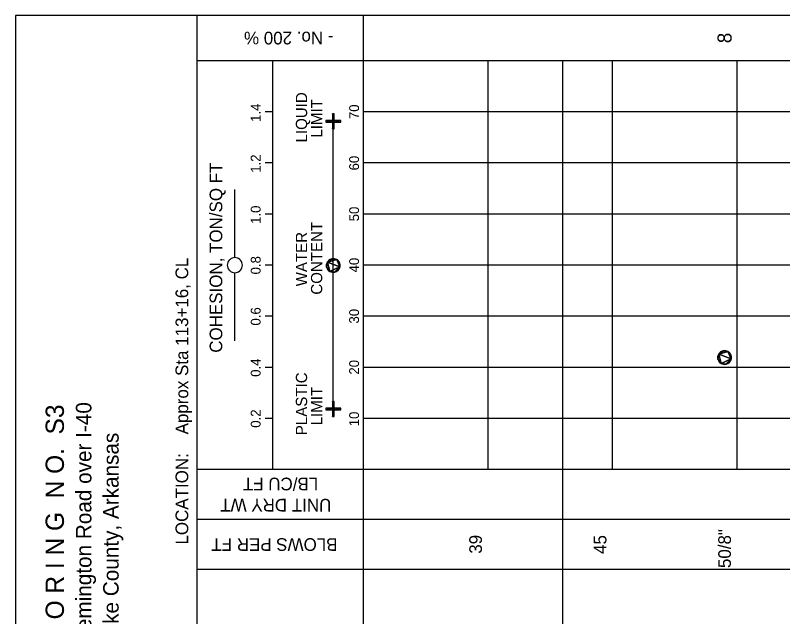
# Model space of a CAD drawing. Extents: x 1313964 to 1316843, y 2087046 to 2096619.
# Drawn here: x 1314173.48 to 1314204.3, y 2089946.89 to 2089971.04 of the extents above; entities that cross this region are included whole.
import ezdxf

# ---------------------------------------------------------------- set-up
doc = ezdxf.new("R2010")
doc.units = 0
doc.layers.add('B-Sub-Contour', color=7, linetype='Continuous')
doc.layers.add('Default', color=7, linetype='Continuous')

# ---------------------------------------------------------------- blocks, each defined once
blk = doc.blocks.new('POINT_DISPLAY')
at = {"layer": 'Default'}
blk.add_line((0, 0), (0, 0), dxfattribs=at)
blk = doc.blocks.new('DMK_101')
at = {"layer": 'Default'}
for points in [[(-14269.212, 2386.584), (-14476.476, 0), (-14269.212, -2386.584), (-14269.212, 2386.584)], [(-12638.532, 6858), (-13653.516, 4690.872), (-14269.212, 2386.584), (-12638.532, 6858)], [(-12638.532, 6858), (-14269.212, 2386.584), (-14269.212, -2386.584), (-12638.532, 6858)], [(-12638.532, 6858), (-14269.212, -2386.584), (-3147.06, -13508.736), (-12638.532, 6858)], [(-3147.06, 13511.784), (-7618.476, 11878.056), (-12638.532, 6858), (-3147.06, 13511.784)], [(6097.524, 11878.056), (-3147.06, 13511.784), (-12638.532, 6858), (6097.524, 11878.056)], [(-7618.476, 11878.056), (-11266.932, 8820.912), (-12638.532, 6858), (-7618.476, 11878.056)], [(-3147.06, -13508.736), (6097.524, 11878.056), (-12638.532, 6858), (-3147.06, -13508.736)], [(-7618.476, 11878.056), (-9578.34, 10506.456), (-11266.932, 8820.912), (-7618.476, 11878.056)], [(-9578.34, 10506.456), (-10456.164, 9698.736), (-11266.932, 8820.912), (-9578.34, 10506.456)], [(-3147.06, 13511.784), (-5451.348, 12893.04), (-7618.476, 11878.056), (-3147.06, 13511.784)], [(1626.108, 13511.784), (-760.476, 13712.952), (-3147.06, 13511.784), (1626.108, 13511.784)], [(6097.524, 11878.056), (1626.108, 13511.784), (-3147.06, 13511.784), (6097.524, 11878.056)], [(-3147.06, -13508.736), (11117.58, -6858), (6097.524, 11878.056), (-3147.06, -13508.736)], [(6097.524, 11878.056), (3930.396, 12893.04), (1626.108, 13511.784), (6097.524, 11878.056)], [(11117.58, 6858), (8060.436, 10506.456), (6097.524, 11878.056), (11117.58, 6858)], [(12751.308, 2386.584), (11117.58, 6858), (6097.524, 11878.056), (12751.308, 2386.584)], [(11117.58, -6858), (12751.308, 2386.584), (6097.524, 11878.056), (11117.58, -6858)], [(9745.98, 8820.912), (8938.26, 9698.736), (8060.436, 10506.456), (9745.98, 8820.912)], [(11117.58, 6858), (9745.98, 8820.912), (8060.436, 10506.456), (11117.58, 6858)], [(12751.308, 2386.584), (12132.564, 4690.872), (11117.58, 6858), (12751.308, 2386.584)], [(11117.58, -6858), (12751.308, -2386.584), (12751.308, 2386.584), (11117.58, -6858)], [(12751.308, -2386.584), (12952.476, 0), (12751.308, 2386.584), (12751.308, -2386.584)], [(-14269.212, -2386.584), (-13653.516, -4690.872), (-12638.532, -6858), (-14269.212, -2386.584)], [(-14269.212, -2386.584), (-12638.532, -6858), (-9578.34, -10506.456), (-14269.212, -2386.584)], [(-14269.212, -2386.584), (-9578.34, -10506.456), (-3147.06, -13508.736), (-14269.212, -2386.584)], [(-12638.532, -6858), (-11266.932, -8817.864), (-9578.34, -10506.456), (-12638.532, -6858)], [(-11266.932, -8817.864), (-10456.164, -9695.688), (-9578.34, -10506.456), (-11266.932, -8817.864)], [(-9578.34, -10506.456), (-7618.476, -11878.056), (-3147.06, -13508.736), (-9578.34, -10506.456)], [(-7618.476, -11878.056), (-5451.348, -12893.04), (-3147.06, -13508.736), (-7618.476, -11878.056)], [(-3147.06, -13508.736), (6097.524, -11878.056), (11117.58, -6858), (-3147.06, -13508.736)], [(-3147.06, -13508.736), (1626.108, -13508.736), (6097.524, -11878.056), (-3147.06, -13508.736)], [(-3147.06, -13508.736), (-760.476, -13716), (1626.108, -13508.736), (-3147.06, -13508.736)], [(1626.108, -13508.736), (3930.396, -12893.04), (6097.524, -11878.056), (1626.108, -13508.736)], [(6097.524, -11878.056), (8060.436, -10506.456), (11117.58, -6858), (6097.524, -11878.056)], [(8060.436, -10506.456), (9745.98, -8817.864), (11117.58, -6858), (8060.436, -10506.456)], [(8060.436, -10506.456), (8938.26, -9695.688), (9745.98, -8817.864), (8060.436, -10506.456)], [(11117.58, -6858), (12132.564, -4690.872), (12751.308, -2386.584), (11117.58, -6858)]]:
    blk.add_lwpolyline(points, close=True, dxfattribs=at)
blk.add_blockref('POINT_DISPLAY', (14479.524, 0), dxfattribs=at)
blk = doc.blocks.new('DMK_7')
at = {"layer": 'Default'}
blk.add_lwpolyline([(0, -15240), (2651.76, -15011.4), (5212.08, -14325.6), (7620, -13197.84), (9799.32, -11673.84), (10774.68, -10774.68), (11673.84, -9799.32), (13197.84, -7620), (14325.6, -5212.08), (15011.4, -2651.76), (15240, 0), (15011.4, 2651.76), (14325.6, 5212.08), (13197.84, 7620), (11673.84, 9799.32), (10774.68, 10774.68), (9799.32, 11673.84), (7620, 13197.84), (5212.08, 14325.6), (2651.76, 15011.4), (0, 15240), (-2651.76, 15011.4), (-5212.08, 14325.6), (-7620, 13197.84), (-9799.32, 11673.84), (-10774.68, 10774.68), (-11673.84, 9799.32), (-13197.84, 7620), (-14325.6, 5212.08), (-15011.4, 2651.76), (-15240, 0), (-15011.4, -2651.76), (-14325.6, -5212.08), (-13197.84, -7620), (-11673.84, -9799.32), (-10774.68, -10774.68), (-9799.32, -11673.84), (-7620, -13197.84), (-5212.08, -14325.6), (-2651.76, -15011.4), (0, -15240)], dxfattribs=at)
blk = doc.blocks.new('DMK_99')
at = {"layer": 'Default'}
for points in [[(-1524, -1524), (-1524, 1524), (-15240, 1524), (-1524, -1524)], [(-1524, -1524), (-15240, 1524), (-15240, -1524), (-1524, -1524)], [(1524, 1524), (1524, 15240), (-1524, 15240), (1524, 1524)], [(1524, 1524), (-1524, 15240), (-1524, 1524), (1524, 1524)], [(-1524, -1524), (1524, -1524), (1524, 1524), (-1524, -1524)], [(-1524, -1524), (1524, 1524), (-1524, 1524), (-1524, -1524)], [(1524, -1524), (15240, -1524), (15240, 1524), (1524, -1524)], [(1524, -1524), (15240, 1524), (1524, 1524), (1524, -1524)], [(-1524, -1524), (-1524, -15240), (1524, -15240), (-1524, -1524)], [(-1524, -1524), (1524, -15240), (1524, -1524), (-1524, -1524)]]:
    blk.add_lwpolyline(points, close=True, dxfattribs=at)

msp = doc.modelspace()

# ---------------------------------------------------------------- linework, layer by layer
at = {"layer": 'B-Sub-Contour'}
for points in [[(1314234.904, 2089928.164), (1314234.904, 2089971.035), (1314173.485, 2089971.035), (1314173.485, 2089928.164), (1314234.904, 2089928.164)], [(1314180.782, 2089928.164), (1314180.782, 2089971.035)], [(1314187.471, 2089928.164), (1314187.471, 2089971.035)], [(1314232.471, 2089969.211), (1314180.782, 2089969.211)], [(1314183.823, 2089969.211), (1314183.519, 2089969.211)], [(1314183.823, 2089952.792), (1314183.823, 2089969.211)], [(1314232.471, 2089969.211), (1314187.471, 2089969.211)], [(1314187.471, 2089952.792), (1314187.471, 2089969.211)], [(1314192.471, 2089952.792), (1314192.471, 2089969.211)], [(1314195.471, 2089948.779), (1314195.471, 2089969.211)], [(1314197.471, 2089952.792), (1314197.471, 2089969.211)], [(1314202.471, 2089952.792), (1314202.471, 2089969.211)], [(1314183.823, 2089967.159), (1314183.519, 2089967.159)], [(1314232.471, 2089967.159), (1314187.471, 2089967.159)], [(1314186.255, 2089955.225), (1314186.255, 2089966.779)], [(1314183.823, 2089965.106), (1314183.519, 2089965.106)], [(1314232.471, 2089965.106), (1314187.471, 2089965.106)], [(1314182.302, 2089961.306), (1314182.302, 2089964.042)], [(1314183.823, 2089963.054), (1314183.519, 2089963.054)], [(1314232.471, 2089963.054), (1314187.471, 2089963.054)], [(1314183.823, 2089961.002), (1314183.519, 2089961.002)], [(1314232.471, 2089961.002), (1314187.471, 2089961.002)], [(1314182.302, 2089957.961), (1314182.302, 2089960.698)], [(1314183.823, 2089958.949), (1314183.519, 2089958.949)], [(1314232.471, 2089958.949), (1314187.471, 2089958.949)], [(1314183.823, 2089956.897), (1314183.519, 2089956.897)], [(1314232.471, 2089956.897), (1314187.471, 2089956.897)], [(1314183.823, 2089954.845), (1314183.519, 2089954.845)], [(1314232.471, 2089954.845), (1314187.471, 2089954.845)], [(1314232.471, 2089952.792), (1314180.782, 2089952.792)], [(1314183.823, 2089952.792), (1314183.519, 2089952.792)], [(1314232.471, 2089952.792), (1314187.471, 2089952.792)], [(1314232.471, 2089950.785), (1314180.782, 2089950.785)], [(1314232.471, 2089948.779), (1314180.782, 2089948.779)], [(1314195.471, 2089932.907), (1314195.471, 2089948.779)]]:
    msp.add_lwpolyline(points, dxfattribs=at)

# ---------------------------------------------------------------- block references
at = {"layer": 'B-Sub-Contour', "xscale": 1.9951013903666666e-05, "yscale": 1.9951013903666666e-05, "rotation": 90}
for name, p in [('DMK_99', (1314186.255, 2089966.779)), ('DMK_7', (1314182.302, 2089961.002)), ('DMK_101', (1314186.255, 2089961.002)), ('DMK_101', (1314201.971, 2089957.307)), ('DMK_101', (1314201.971, 2089957.307)), ('DMK_99', (1314186.255, 2089955.225))]:
    msp.add_blockref(name, p, dxfattribs=at)

# ---------------------------------------------------------------- texts
at = {"layer": 'B-Sub-Contour'}
for s, height, rotation, p in [('- No. 200 %', 0.50899, 180, (1314186.263, 2089970.378)), ('8', 0.566, 90, (1314202.254, 2089969.916)), ('LIQUID', 0.4524, 90, (1314185.204, 2089965.93)), ('1.4', 0.3959, 90, (1314183.336, 2089966.757)), ('LIMIT', 0.4524, 90, (1314185.812, 2089966.123)), ('70', 0.3959, 90, (1314187.289, 2089966.868)), ('1.2', 0.3959, 90, (1314183.336, 2089964.712)), ('60', 0.3959, 90, (1314187.289, 2089964.808)), ('COHESION, TON/SQ FT', 0.50899, 90, (1314181.797, 2089957.485)), ('1.0', 0.3959, 90, (1314183.336, 2089962.66)), ('50', 0.3959, 90, (1314187.289, 2089962.763)), ('CONTENT', 0.4524, 90, (1314185.812, 2089959.817)), ('WATER', 0.4524, 90, (1314185.204, 2089960.153)), ('LOCATION:    Approx Sta 113+16, CL', 0.50899, 90, (1314180.428, 2089949.782)), ('0.8', 0.3959, 90, (1314183.336, 2089960.63)), ('40', 0.3959, 90, (1314187.289, 2089960.711)), ('0.6', 0.3959, 90, (1314183.336, 2089958.577)), ('30', 0.3959, 90, (1314187.289, 2089958.658)), ('0.4', 0.3959, 90, (1314183.336, 2089956.518)), ('20', 0.3959, 90, (1314187.289, 2089956.606)), ('PLASTIC', 0.4524, 90, (1314185.204, 2089954.174)), ('LIMIT', 0.4524, 90, (1314185.812, 2089954.569)), ('061610 - Remington Road over I-40', 0.62209, 90, (1314176.539, 2089942.229)), ('L O G  O F  B O R I N G  N O.  S3', 0.7352, 90, (1314175.436, 2089940.493)), ('0.2', 0.3959, 90, (1314183.336, 2089954.473)), ('10', 0.3959, 90, (1314187.289, 2089954.531)), ('Lonoke County, Arkansas', 0.62209, 90, (1314177.634, 2089944.747)), ('LB/CU FT', 0.509, 180, (1314185.649, 2089952.469)), ('UNIT DRY WT', 0.50899, 180, (1314186.178, 2089951.618)), ('39', 0.509, 90, (1314192.226, 2089949.413)), ('45', 0.509, 90, (1314197.226, 2089949.404)), ('50/8"', 0.509, 90, (1314202.226, 2089948.837)), ('BLOWS PER FT', 0.50899, 180, (1314186.424, 2089950.037))]:
    msp.add_text(s, height=height, rotation=rotation, dxfattribs=at).set_placement(p)

doc.saveas('drawing.dxf')
